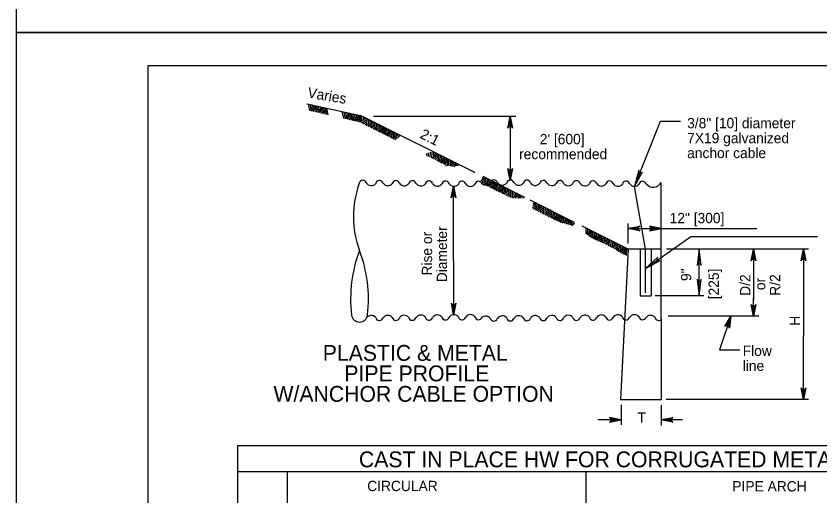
# Model space of a CAD drawing. Extents: x 1083.1 to 1117.1, y 675.4 to 741.4.
# Drawn here: x 1083.13 to 1095.29, y 712.34 to 719.6 of the extents above; entities that cross this region are included whole.
import ezdxf

# ---------------------------------------------------------------- set-up
doc = ezdxf.new("R2010")
doc.units = 0
doc.layers.add('Level 1', color=7, linetype='Continuous')
doc.layers.add('Level 44', color=7, linetype='Continuous')

msp = doc.modelspace()

# ---------------------------------------------------------------- linework, layer by layer
at = {"layer": 'Level 1'}
for p, q in [((1087.527, 718.276), (1088.342, 718.102)), ((1087.572, 718.175), (1087.551, 718.277)), ((1087.571, 718.173), (1087.636, 718.257)), ((1087.593, 718.202), (1087.578, 718.27)), ((1087.597, 718.167), (1087.659, 718.247)), ((1087.611, 718.226), (1087.603, 718.265)), ((1087.623, 718.161), (1087.666, 718.215)), ((1087.651, 718.154), (1087.673, 718.183)), ((1087.68, 718.148), (1087.658, 718.252)), ((1087.702, 718.146), (1087.681, 718.247)), ((1087.7, 718.143), (1087.766, 718.228)), ((1087.721, 718.17), (1087.706, 718.241)), ((1087.724, 718.138), (1087.787, 718.219)), ((1087.741, 718.195), (1087.733, 718.235)), ((1087.749, 718.132), (1087.793, 718.189)), ((1087.774, 718.126), (1087.8, 718.159)), ((1087.808, 718.118), (1087.787, 718.222)), ((1087.831, 718.117), (1087.81, 718.217)), ((1087.851, 718.111), (1087.83, 718.212)), ((1088.087, 718.054), (1088.065, 718.158)), ((1088.114, 718.05), (1088.093, 718.152)), ((1088.112, 718.048), (1088.177, 718.132)), ((1088.134, 718.077), (1088.12, 718.145)), ((1088.138, 718.042), (1088.2, 718.122)), ((1088.153, 718.101), (1088.145, 718.14)), ((1088.165, 718.036), (1088.207, 718.09)), ((1088.192, 718.029), (1088.214, 718.058)), ((1088.222, 718.023), (1088.199, 718.127)), ((1088.244, 718.021), (1088.222, 718.122)), ((1088.242, 718.018), (1088.307, 718.103)), ((1088.263, 718.045), (1088.248, 718.116)), ((1088.265, 718.013), (1088.328, 718.094)), ((1088.282, 718.07), (1088.274, 718.11)), ((1088.291, 718.007), (1088.335, 718.064)), ((1088.316, 718.001), (1088.341, 718.034)), ((1088.35, 717.993), (1088.328, 718.097)), ((1090.072, 717.237), (1088.342, 718.102)), ((1088.347, 718.007), (1088.418, 718.064)), ((1088.366, 718.022), (1088.351, 718.092)), ((1088.361, 717.985), (1088.44, 718.048)), ((1088.389, 718.041), (1088.382, 718.082)), ((1088.437, 717.946), (1088.44, 718.053)), ((1088.462, 717.937), (1088.465, 718.04)), ((1090.69, 718.087), (1088.538, 718.087)), ((1090.582, 717.925), (1090.606, 718.087)), ((1090.592, 717.931), (1090.606, 718.087)), ((1090.606, 718.087), (1090.606, 717.123)), ((1090.606, 717.934), (1090.606, 718.087)), ((1090.618, 717.933), (1090.606, 718.087)), ((1090.629, 717.927), (1090.606, 718.087)), ((1088.385, 717.972), (1088.439, 718.016)), ((1088.41, 717.96), (1088.438, 717.983)), ((1088.46, 717.935), (1088.543, 718.002)), ((1088.484, 717.923), (1088.563, 717.986)), ((1088.488, 717.958), (1088.49, 718.028)), ((1088.509, 717.911), (1088.562, 717.954)), ((1088.512, 717.977), (1088.513, 718.016)), ((1088.534, 717.898), (1088.562, 717.921)), ((1088.561, 717.885), (1088.563, 717.991)), ((1088.579, 717.876), (1088.662, 717.942)), ((1088.582, 717.878), (1088.585, 717.981)), ((1088.601, 717.865), (1088.681, 717.929)), ((1088.606, 717.897), (1088.608, 717.969)), ((1088.631, 717.917), (1088.632, 717.957)), ((1088.678, 717.826), (1088.682, 717.932)), ((1088.7, 717.817), (1088.703, 717.922)), ((1088.719, 717.809), (1088.722, 717.912)), ((1092.487, 717.028), (1092.88, 718.014)), ((1092.88, 718.014), (1093.186, 718.014)), ((1088.624, 717.853), (1088.68, 717.898)), ((1088.647, 717.842), (1088.68, 717.868)), ((1088.716, 717.807), (1088.799, 717.874)), ((1088.737, 717.796), (1088.818, 717.861)), ((1088.743, 717.828), (1088.745, 717.901)), ((1088.761, 717.785), (1088.817, 717.83)), ((1088.768, 717.848), (1088.769, 717.889)), ((1088.784, 717.773), (1088.816, 717.799)), ((1088.815, 717.757), (1088.819, 717.864)), ((1088.832, 717.749), (1088.915, 717.816)), ((1088.837, 717.753), (1088.838, 717.804)), ((1088.838, 717.804), (1088.84, 717.853)), ((1088.858, 717.736), (1088.937, 717.799)), ((1088.859, 717.771), (1088.861, 717.843)), ((1088.883, 717.79), (1088.885, 717.831)), ((1089.342, 717.491), (1089.343, 717.523)), ((1089.369, 717.478), (1089.37, 717.536)), ((1089.395, 717.468), (1089.398, 717.543)), ((1089.42, 717.455), (1089.503, 717.522)), ((1089.422, 717.457), (1089.425, 717.544)), ((1089.444, 717.443), (1089.523, 717.506)), ((1089.448, 717.478), (1089.45, 717.543)), ((1089.468, 717.431), (1089.522, 717.474)), ((1089.472, 717.497), (1089.473, 717.537)), ((1089.494, 717.418), (1089.521, 717.441)), ((1089.52, 717.405), (1089.523, 717.512)), ((1089.539, 717.396), (1089.622, 717.462)), ((1089.541, 717.398), (1089.544, 717.501)), ((1089.56, 717.385), (1089.641, 717.449)), ((1089.565, 717.417), (1089.568, 717.489)), ((1089.591, 717.437), (1089.592, 717.477)), ((1089.638, 717.333), (1089.641, 717.453)), ((1089.66, 717.338), (1089.663, 717.442)), ((1089.679, 717.342), (1089.681, 717.433)), ((1089.584, 717.373), (1089.64, 717.419)), ((1089.607, 717.362), (1089.639, 717.388)), ((1089.693, 717.341), (1089.759, 717.394)), ((1089.702, 717.348), (1089.705, 717.421)), ((1089.719, 717.334), (1089.778, 717.381)), ((1089.728, 717.369), (1089.729, 717.409)), ((1089.752, 717.33), (1089.777, 717.35)), ((1089.777, 717.331), (1089.778, 717.384)), ((1089.799, 717.337), (1089.8, 717.373)), ((1089.82, 717.338), (1089.821, 717.363)), ((1090.068, 717.231), (1090.068, 717.239)), ((1090.584, 717.283), (1090.606, 717.123)), ((1090.595, 717.278), (1090.606, 717.123)), ((1090.631, 717.285), (1090.606, 717.123)), ((1090.621, 717.279), (1090.606, 717.123)), ((1090.606, 717.276), (1090.606, 717.123)), ((1090.167, 717.116), (1090.224, 717.161)), ((1090.168, 717.086), (1090.244, 717.146)), ((1090.168, 717.118), (1090.168, 717.119)), ((1090.168, 717.119), (1090.168, 717.119)), ((1090.189, 717.071), (1090.243, 717.114)), ((1090.192, 717.137), (1090.194, 717.169)), ((1090.194, 717.169), (1090.194, 717.169)), ((1090.826, 716.86), (1090.197, 717.175)), ((1090.214, 717.058), (1090.242, 717.081)), ((1090.241, 717.045), (1090.244, 717.151)), ((1090.259, 717.035), (1090.343, 717.102)), ((1090.262, 717.038), (1090.265, 717.141)), ((1090.281, 717.025), (1090.361, 717.089)), ((1090.286, 717.057), (1090.288, 717.129)), ((1090.311, 717.077), (1090.312, 717.117)), ((1090.359, 716.986), (1090.362, 717.092)), ((1090.38, 716.97), (1090.383, 717.076)), ((1090.399, 716.969), (1090.402, 717.072)), ((1090.423, 716.988), (1090.425, 717.061)), ((1092.891, 715.029), (1092.891, 717.085)), ((1089.723, 716.871), (1089.748, 717.033)), ((1089.734, 716.877), (1089.748, 717.033)), ((1089.748, 716.88), (1089.748, 717.033)), ((1089.759, 716.878), (1089.748, 717.033)), ((1089.77, 716.872), (1089.748, 717.033)), ((1089.748, 715.903), (1089.748, 717.03)), ((1090.304, 717.013), (1090.361, 717.058)), ((1090.327, 717.002), (1090.36, 717.028)), ((1090.396, 716.967), (1090.48, 717.034)), ((1090.418, 716.956), (1090.498, 717.021)), ((1090.441, 716.944), (1090.498, 716.99)), ((1090.448, 717.008), (1090.449, 717.049)), ((1090.464, 716.933), (1090.497, 716.959)), ((1090.496, 716.917), (1090.499, 717.024)), ((1090.512, 716.909), (1090.596, 716.976)), ((1090.517, 716.913), (1090.519, 716.964)), ((1090.519, 716.964), (1090.52, 717.013)), ((1090.538, 716.896), (1090.618, 716.959)), ((1090.54, 716.931), (1090.542, 717.003)), ((1090.564, 716.95), (1090.565, 716.991)), ((1090.615, 716.858), (1090.618, 716.964)), ((1090.64, 716.853), (1090.643, 716.952)), ((1090.666, 716.869), (1090.668, 716.939)), ((1092.654, 716.078), (1092.487, 717.028)), ((1090.563, 716.884), (1090.617, 716.927)), ((1090.587, 716.872), (1090.616, 716.895)), ((1090.646, 716.853), (1090.721, 716.913)), ((1090.683, 716.852), (1090.741, 716.898)), ((1090.689, 716.889), (1090.691, 716.928)), ((1090.722, 716.851), (1090.74, 716.865)), ((1090.74, 716.85), (1090.741, 716.903)), ((1090.761, 716.85), (1090.762, 716.892)), ((1090.784, 716.849), (1090.785, 716.881)), ((1090.809, 716.848), (1090.81, 716.869)), ((1091.58, 716.483), (1090.91, 716.818)), ((1090.946, 716.702), (1090.995, 716.741)), ((1090.951, 716.737), (1090.995, 716.772)), ((1090.955, 716.768), (1090.977, 716.785)), ((1090.961, 716.685), (1090.994, 716.711)), ((1090.993, 716.669), (1090.996, 716.775)), ((1091.009, 716.661), (1091.093, 716.727)), ((1091.014, 716.665), (1091.016, 716.715)), ((1091.016, 716.715), (1091.017, 716.765)), ((1091.035, 716.648), (1091.115, 716.711)), ((1091.037, 716.682), (1091.039, 716.754)), ((1091.061, 716.702), (1091.062, 716.742)), ((1091.112, 716.609), (1091.115, 716.716)), ((1091.137, 716.6), (1091.14, 716.703)), ((1091.06, 716.635), (1091.114, 716.678)), ((1091.084, 716.623), (1091.113, 716.646)), ((1091.135, 716.598), (1091.218, 716.664)), ((1091.159, 716.586), (1091.238, 716.649)), ((1091.163, 716.62), (1091.165, 716.691)), ((1091.183, 716.574), (1091.237, 716.617)), ((1091.187, 716.64), (1091.188, 716.679)), ((1091.208, 716.561), (1091.236, 716.583)), ((1091.235, 716.548), (1091.238, 716.654)), ((1091.254, 716.538), (1091.337, 716.605)), ((1091.256, 716.54), (1091.259, 716.644)), ((1091.275, 716.528), (1091.356, 716.592)), ((1091.28, 716.56), (1091.283, 716.632)), ((1091.305, 716.58), (1091.307, 716.62)), ((1091.353, 716.489), (1091.356, 716.595)), ((1091.374, 716.483), (1091.378, 716.584)), ((1091.393, 716.478), (1091.396, 716.575)), ((1091.299, 716.516), (1091.355, 716.561)), ((1091.322, 716.505), (1091.354, 716.531)), ((1091.399, 716.477), (1091.474, 716.537)), ((1091.417, 716.491), (1091.419, 716.564)), ((1091.426, 716.47), (1091.493, 716.524)), ((1091.442, 716.511), (1091.444, 716.552)), ((1091.454, 716.462), (1091.492, 716.493)), ((1091.482, 716.455), (1091.491, 716.462)), ((1091.491, 716.452), (1091.493, 716.527)), ((1091.513, 716.466), (1091.515, 716.516)), ((1091.513, 716.446), (1091.513, 716.466)), ((1091.534, 716.44), (1091.536, 716.505)), ((1091.539, 716.438), (1091.58, 716.471)), ((1091.558, 716.453), (1091.559, 716.494)), ((1092.39, 716.161), (1092.39, 716.467)), ((1092.39, 716.078), (1091.697, 716.425)), ((1091.754, 716.312), (1091.756, 716.395)), ((1091.765, 716.302), (1091.834, 716.357)), ((1091.777, 716.311), (1091.78, 716.384)), ((1091.783, 716.288), (1091.853, 716.344)), ((1091.803, 716.331), (1091.804, 716.371)), ((1091.85, 716.245), (1091.853, 716.347)), ((1091.871, 716.235), (1091.875, 716.336)), ((1092.551, 716.413), (1092.39, 716.39)), ((1092.545, 716.402), (1092.39, 716.39)), ((1092.39, 716.39), (1094.338, 716.39)), ((1092.544, 716.39), (1092.39, 716.39)), ((1092.546, 716.376), (1092.39, 716.39)), ((1092.553, 716.365), (1092.39, 716.39)), ((1092.729, 716.365), (1092.891, 716.39)), ((1092.731, 716.413), (1092.891, 716.39)), ((1092.736, 716.376), (1092.891, 716.39)), ((1092.737, 716.402), (1092.891, 716.39)), ((1092.738, 716.39), (1092.891, 716.39)), ((1091.803, 716.273), (1091.852, 716.313)), ((1091.824, 716.26), (1091.851, 716.282)), ((1091.89, 716.226), (1091.893, 716.327)), ((1091.892, 716.225), (1091.971, 716.288)), ((1091.914, 716.243), (1091.917, 716.315)), ((1091.914, 716.215), (1091.99, 716.275)), ((1091.938, 716.204), (1091.989, 716.244)), ((1091.939, 716.263), (1091.941, 716.303)), ((1091.962, 716.193), (1091.988, 716.214)), ((1091.987, 716.182), (1091.99, 716.278)), ((1092.009, 716.173), (1092.01, 716.218)), ((1092.01, 716.218), (1092.012, 716.268)), ((1092.013, 716.171), (1092.087, 716.23)), ((1092.031, 716.185), (1092.033, 716.257)), ((1092.039, 716.158), (1092.109, 716.214)), ((1092.055, 716.205), (1092.057, 716.245)), ((1092.106, 716.125), (1092.109, 716.219)), ((1092.654, 715.785), (1093.338, 716.27)), ((1093.338, 716.27), (1095.26, 716.27)), ((1092.064, 716.146), (1092.108, 716.181)), ((1092.088, 716.134), (1092.107, 716.149)), ((1092.131, 716.112), (1092.134, 716.206)), ((1092.139, 716.109), (1092.212, 716.167)), ((1092.157, 716.123), (1092.159, 716.194)), ((1092.162, 716.097), (1092.232, 716.152)), ((1092.181, 716.143), (1092.182, 716.182)), ((1092.187, 716.084), (1092.231, 716.12)), ((1092.211, 716.071), (1092.23, 716.086)), ((1092.229, 716.054), (1092.232, 716.157)), ((1092.248, 716.041), (1092.331, 716.108)), ((1092.25, 716.043), (1092.253, 716.147)), ((1092.269, 716.031), (1092.35, 716.095)), ((1092.274, 716.063), (1092.277, 716.135)), ((1092.3, 716.083), (1092.301, 716.123)), ((1092.347, 715.992), (1092.35, 716.098)), ((1092.369, 715.984), (1092.372, 716.087)), ((1092.39, 716.078), (1092.274, 713.801)), ((1092.293, 716.019), (1092.349, 716.064)), ((1092.316, 716.007), (1092.348, 716.034)), ((1092.891, 716.078), (1092.39, 716.078)), ((1092.571, 716.078), (1092.571, 715.372)), ((1092.654, 715.418), (1092.654, 716.078)), ((1092.738, 716.078), (1092.738, 715.372)), ((1095.12, 716.078), (1092.973, 716.078)), ((1093.467, 715.372), (1093.467, 716.078)), ((1094.263, 715.916), (1094.288, 716.078)), ((1094.274, 715.922), (1094.288, 716.078)), ((1094.288, 715.925), (1094.288, 716.078)), ((1094.299, 715.923), (1094.288, 716.078)), ((1094.31, 715.918), (1094.288, 716.078)), ((1094.288, 716.078), (1094.288, 715.311)), ((1095.022, 715.916), (1095.047, 716.078)), ((1095.033, 715.922), (1095.047, 716.078)), ((1095.047, 716.078), (1095.047, 714.766)), ((1095.047, 715.925), (1095.047, 716.078)), ((1095.059, 715.923), (1095.047, 716.078)), ((1095.07, 715.918), (1095.047, 716.078)), ((1089.748, 715.903), (1089.748, 715.085)), ((1092.571, 715.372), (1092.738, 715.372)), ((1093.535, 715.372), (1092.798, 715.372)), ((1089.727, 715.245), (1089.75, 715.085)), ((1089.739, 715.24), (1089.75, 715.085)), ((1089.775, 715.247), (1089.75, 715.085)), ((1089.764, 715.241), (1089.75, 715.085)), ((1089.75, 715.238), (1089.75, 715.085)), ((1094.288, 715.064), (1094.288, 715.334)), ((1094.266, 715.224), (1094.288, 715.064)), ((1094.277, 715.218), (1094.288, 715.064)), ((1094.313, 715.226), (1094.288, 715.064)), ((1094.302, 715.22), (1094.288, 715.064)), ((1094.288, 715.217), (1094.288, 715.064)), ((1092.891, 715.029), (1092.891, 714.741)), ((1094.371, 715.064), (1092.996, 715.064)), ((1093.871, 714.917), (1093.945, 715.064)), ((1093.883, 714.919), (1093.945, 715.064)), ((1093.898, 714.918), (1093.945, 715.064)), ((1093.908, 714.913), (1093.945, 715.064)), ((1093.917, 714.904), (1093.945, 715.064)), ((1095.047, 713.801), (1095.047, 714.766)), ((1092.891, 714.741), (1092.891, 713.801)), ((1095.025, 713.961), (1095.047, 713.801)), ((1095.036, 713.956), (1095.047, 713.801)), ((1095.072, 713.963), (1095.047, 713.801)), ((1095.062, 713.957), (1095.047, 713.801)), ((1095.047, 713.954), (1095.047, 713.801)), ((1092.274, 713.801), (1092.891, 713.801)), ((1095.12, 713.801), (1092.966, 713.801)), ((1092.285, 713.724), (1092.285, 713.419)), ((1092.891, 713.718), (1092.891, 713.412)), ((1092.285, 713.495), (1091.932, 713.495)), ((1092.123, 713.471), (1092.285, 713.495)), ((1092.124, 713.518), (1092.285, 713.495)), ((1092.129, 713.481), (1092.285, 713.495)), ((1092.13, 713.507), (1092.285, 713.495)), ((1092.132, 713.495), (1092.285, 713.495)), ((1093.052, 713.518), (1092.891, 713.495)), ((1093.046, 713.507), (1092.891, 713.495)), ((1093.213, 713.495), (1092.891, 713.495)), ((1093.045, 713.495), (1092.891, 713.495)), ((1093.047, 713.481), (1092.891, 713.495)), ((1093.054, 713.471), (1092.891, 713.495)), ((1086.478, 713.109), (1086.473, 698.26)), ((1086.478, 713.109), (1103.658, 713.109)), ((1103.658, 712.709), (1086.478, 712.709)), ((1087.228, 712.709), (1087.223, 699.159)), ((1091.754, 699.159), (1091.754, 712.709))]:
    msp.add_line(p, q, dxfattribs=at)
for points in [[(1083.126, 719.354), (1117.126, 719.354), (1117.126, 741.354), (1083.126, 741.354)], [(1083.126, 697.354), (1117.126, 697.354), (1117.126, 719.354), (1083.126, 719.354)], [(1083.126, 697.354), (1117.126, 697.354), (1117.126, 719.354), (1083.126, 719.354)], [(1085.126, 718.854), (1116.626, 718.854), (1116.626, 697.854), (1085.126, 697.854)]]:
    msp.add_lwpolyline(points, close=True, dxfattribs=at)
for points in [[(1090.571, 717.91), (1090.606, 718.087), (1090.642, 717.91)], [(1090.642, 717.3), (1090.606, 717.123), (1090.571, 717.3)], [(1089.712, 716.856), (1089.748, 717.033), (1089.783, 716.856)], [(1092.567, 716.355), (1092.39, 716.39), (1092.567, 716.426)], [(1092.715, 716.355), (1092.891, 716.39), (1092.715, 716.426)], [(1094.253, 715.901), (1094.288, 716.078), (1094.323, 715.901)], [(1095.012, 715.901), (1095.047, 716.078), (1095.083, 715.901)], [(1089.785, 715.262), (1089.75, 715.085), (1089.715, 715.262)], [(1094.323, 715.241), (1094.288, 715.064), (1094.253, 715.241)], [(1093.945, 715.064), (1093.775, 714.553), (1094.084, 714.553)], [(1093.857, 714.906), (1093.945, 715.064), (1093.924, 714.884)], [(1095.083, 713.978), (1095.047, 713.801), (1095.012, 713.978)], [(1092.108, 713.46), (1092.285, 713.495), (1092.108, 713.531)], [(1093.068, 713.46), (1092.891, 713.495), (1093.068, 713.531)]]:
    msp.add_lwpolyline(points, dxfattribs=at)
for centre, start, end in [((1090.606, 717.896), 22.0878, 157.9139), ((1090.606, 717.314), 202.0878, 337.9139), ((1089.748, 716.841), 22.0878, 157.9139), ((1092.582, 716.39), 112.0878, 247.9139), ((1092.7, 716.39), 292.0861, 67.9122), ((1094.288, 715.887), 22.0878, 157.9139), ((1095.047, 715.887), 22.0878, 157.9139), ((1089.75, 715.276), 202.0878, 337.9139), ((1094.288, 715.255), 202.0878, 337.9139), ((1093.886, 714.881), 4.3457, 140.1718), ((1095.047, 713.992), 202.0878, 337.9139), ((1092.093, 713.495), 292.0861, 67.9122), ((1093.083, 713.495), 112.0878, 247.9139)]:
    msp.add_arc(centre, 0.0382, start, end, dxfattribs=at)
for centre, major_axis, start_param, end_param in [((1089.726, 716.572), (-1.493, 0), 5.937722, 6.635502), ((1088.376, 717.064), (0.056, 0), 0.338176, 2.886862), ((1088.503, 717.128), (0.0877, 0), 3.693284, 5.600053), ((1088.625, 717.062), (0.056, 0), 0.338176, 2.936471), ((1088.753, 717.126), (0.0877, 0), 3.693284, 5.600053), ((1088.876, 717.059), (0.056, 0), 0.338176, 2.936471), ((1089.003, 717.124), (0.0877, 0), 3.693284, 5.600053), ((1089.126, 717.057), (0.056, 0), 0.338176, 2.936471), ((1089.254, 717.122), (0.0877, 0), 3.693284, 5.600053), ((1089.376, 717.055), (0.056, 0), 0.338176, 2.936471), ((1089.504, 717.119), (0.0877, 0), 3.693284, 5.600053), ((1089.627, 717.053), (0.056, 0), 0.338176, 2.936471), ((1089.754, 717.117), (0.0877, 0), 3.693284, 5.600053), ((1089.877, 717.051), (0.056, 0), 0.338176, 2.936471), ((1090.004, 717.115), (0.0877, 0), 3.693284, 5.600053), ((1090.127, 717.048), (0.056, 0), 0.338176, 2.936471), ((1090.235, 717.136), (0.0877, 0), 4.01572, 5.600053), ((1090.358, 717.069), (0.056, 0), 0.338176, 2.936471), ((1090.486, 717.134), (0.0877, 0), 3.693284, 5.600053), ((1090.609, 717.067), (0.056, 0), 0.338176, 2.936471), ((1090.736, 717.131), (0.0877, 0), 3.693284, 5.600053), ((1090.859, 717.065), (0.056, 0), 0.338176, 2.936471), ((1090.986, 717.129), (0.0877, 0), 3.693284, 5.600053), ((1091.109, 717.062), (0.056, 0), 0.338176, 2.936471), ((1091.236, 717.127), (0.0877, 0), 3.693284, 5.600053), ((1091.359, 717.06), (0.056, 0), 0.338176, 2.936471), ((1091.487, 717.125), (0.0877, 0), 3.693284, 5.600053), ((1091.609, 717.058), (0.056, 0), 0.338176, 2.936471), ((1091.737, 717.123), (0.0877, 0), 3.693284, 5.600053), ((1091.86, 717.056), (0.056, 0), 0.338176, 2.936471), ((1091.987, 717.12), (0.0877, 0), 3.693284, 5.600053), ((1092.11, 717.054), (0.056, 0), 0.338176, 2.936471), ((1092.237, 717.118), (0.0877, 0), 3.693284, 5.600053), ((1092.36, 717.051), (0.056, 0), 0.338176, 2.936471), ((1092.487, 717.116), (0.0877, 0), 3.693284, 5.600053), ((1092.61, 717.049), (0.056, 0), 0.338176, 2.936471), ((1092.771, 717.155), (-0.139, 0), 0.676998, 2.618407), ((1090.255, 715.323), (-2.065, 0), 5.919813, 6.398853), ((1086.395, 715.323), (2.065, 0), 6.167517, 6.646557), ((1088.325, 715.097), (-0.122, 0), 0.132192, 1.570796), ((1088.325, 715.097), (0.122, 0), 4.712389, 6.150994), ((1088.503, 714.986), (0.0877, 0), 0.683132, 2.589902), ((1088.625, 715.053), (0.056, 0), 3.346714, 5.94501), ((1088.753, 714.988), (0.0877, 0), 0.683132, 2.589902), ((1088.876, 715.055), (0.056, 0), 3.346714, 5.94501), ((1089.003, 714.99), (0.0877, 0), 0.683132, 2.589902), ((1089.126, 715.057), (0.056, 0), 3.346714, 5.94501), ((1089.254, 714.993), (0.0877, 0), 0.683132, 2.589902), ((1089.376, 715.059), (0.056, 0), 3.346714, 5.94501), ((1089.504, 714.995), (0.0877, 0), 0.683132, 2.589902), ((1089.627, 715.062), (0.056, 0), 3.346714, 5.94501), ((1089.754, 714.997), (0.0877, 0), 0.683132, 2.589902), ((1089.877, 715.064), (0.056, 0), 3.346714, 5.94501), ((1090.004, 714.999), (0.0877, 0), 0.683132, 2.589902), ((1090.127, 715.066), (0.056, 0), 3.346714, 5.94501), ((1090.235, 714.978), (0.0877, 0), 0.683132, 2.296456), ((1090.358, 715.045), (0.056, 0), 3.346714, 5.94501), ((1090.486, 714.981), (0.0877, 0), 0.683132, 2.589902), ((1090.609, 715.047), (0.056, 0), 3.346714, 5.94501), ((1090.736, 714.983), (0.0877, 0), 0.683132, 2.589902), ((1090.859, 715.05), (0.056, 0), 3.346714, 5.94501), ((1090.986, 714.985), (0.0877, 0), 0.683132, 2.589902), ((1091.109, 715.052), (0.056, 0), 3.346714, 5.94501), ((1091.236, 714.987), (0.0877, 0), 0.683132, 2.589902), ((1091.359, 715.054), (0.056, 0), 3.346714, 5.94501), ((1091.487, 714.99), (0.0877, 0), 0.683132, 2.589902), ((1091.609, 715.056), (0.056, 0), 3.346714, 5.94501), ((1091.737, 714.992), (0.0877, 0), 0.683132, 2.589902), ((1091.86, 715.059), (0.056, 0), 3.346714, 5.94501), ((1091.987, 714.994), (0.0877, 0), 0.683132, 2.589902), ((1092.11, 715.061), (0.056, 0), 3.346714, 5.94501), ((1092.237, 714.996), (0.0877, 0), 0.683132, 2.589902), ((1092.36, 715.063), (0.056, 0), 3.346714, 5.94501), ((1092.487, 714.998), (0.0877, 0), 0.683132, 2.589902), ((1092.61, 715.065), (0.056, 0), 3.346714, 5.94501), ((1092.731, 714.988), (0.0877, 0), 0.683132, 2.589902), ((1092.854, 715.055), (0.056, 0), 3.346714, 5.471643)]:
    msp.add_ellipse(centre, major_axis=major_axis, ratio=0.999895, start_param=start_param, end_param=end_param, dxfattribs=at)
at = {"layer": 'Level 44'}
for p, q in [((1092.551, 717.272), (1092.487, 717.028)), ((1092.487, 717.028), (1092.609, 717.249)), ((1093.467, 716.078), (1093.436, 715.828)), ((1093.498, 715.828), (1093.467, 716.078)), ((1092.84, 715.955), (1092.654, 715.785)), ((1092.654, 715.785), (1092.876, 715.904)), ((1093.436, 715.622), (1093.467, 715.372)), ((1093.467, 715.372), (1093.498, 715.622))]:
    msp.add_line(p, q, dxfattribs=at)
for centre, radius, start, end in [((1092.58, 717.26), 0.0312, 158.278, 338.278), ((1092.858, 715.93), 0.0313, 125.3589, 305.3589), ((1093.467, 715.828), 0.0312, 0, 180), ((1093.467, 715.622), 0.0312, 180, 0)]:
    msp.add_arc(centre, radius, start, end, dxfattribs=at)

# ---------------------------------------------------------------- texts
at = {"layer": 'Level 1'}
for s, rotation, p in [('Varies', 350.3559, (1087.53, 718.374)), ('2:1', 333.4374, (1089.227, 717.767)), ('Rise or', 90, (1089.424, 715.679)), ('Diameter', 90, (1089.65, 715.577)), ('9"', 90, (1093.347, 715.595)), ('[225]', 90, (1093.765, 715.319)), ('D/2', 90, (1094.241, 715.372)), ('or', 90, (1094.467, 715.458)), ('R/2', 90, (1094.693, 715.373)), ('H', 90, (1094.994, 714.92))]:
    msp.add_text(s, height=0.156, rotation=rotation, dxfattribs=at).set_placement(p)
for s, height, p in [('3/8" [10] diameter', 0.156, (1093.285, 717.907)), ("2' [600]", 0.156, (1091.054, 717.665)), ('7X19 galvanized', 0.156, (1093.285, 717.681)), ('recommended', 0.156, (1090.741, 717.439)), ('anchor cable', 0.156, (1093.285, 717.455)), ('12" [300]', 0.156, (1093.02, 716.47)), ('PLASTIC & METAL', 0.24, (1087.769, 714.388)), ('Flow', 0.156, (1094.126, 714.462)), ('line', 0.156, (1094.126, 714.236)), ('PIPE PROFILE', 0.24, (1088.096, 714.078)), ('W/ANCHOR CABLE OPTION', 0.24, (1087.023, 713.768)), ('T', 0.156, (1092.532, 713.451)), ('CAST IN PLACE HW FOR CORRUGATED METAL PIPE & PLASTIC PIPE (Metric)', 0.24, (1088.316, 712.777)), ('CIRCULAR', 0.156, (1088.442, 712.417)), ('PIPE ARCH', 0.156, (1093.969, 712.412))]:
    msp.add_text(s, height=height, dxfattribs=at).set_placement(p)

doc.saveas('drawing.dxf')
